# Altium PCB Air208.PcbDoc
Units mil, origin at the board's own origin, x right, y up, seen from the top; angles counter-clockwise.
Board outline 6000 x 4000 mil, 2 copper layers (Top, Bottom), stack 12.7 mil thick; 1 components, 0 nets, 42 pads, 0 vias.
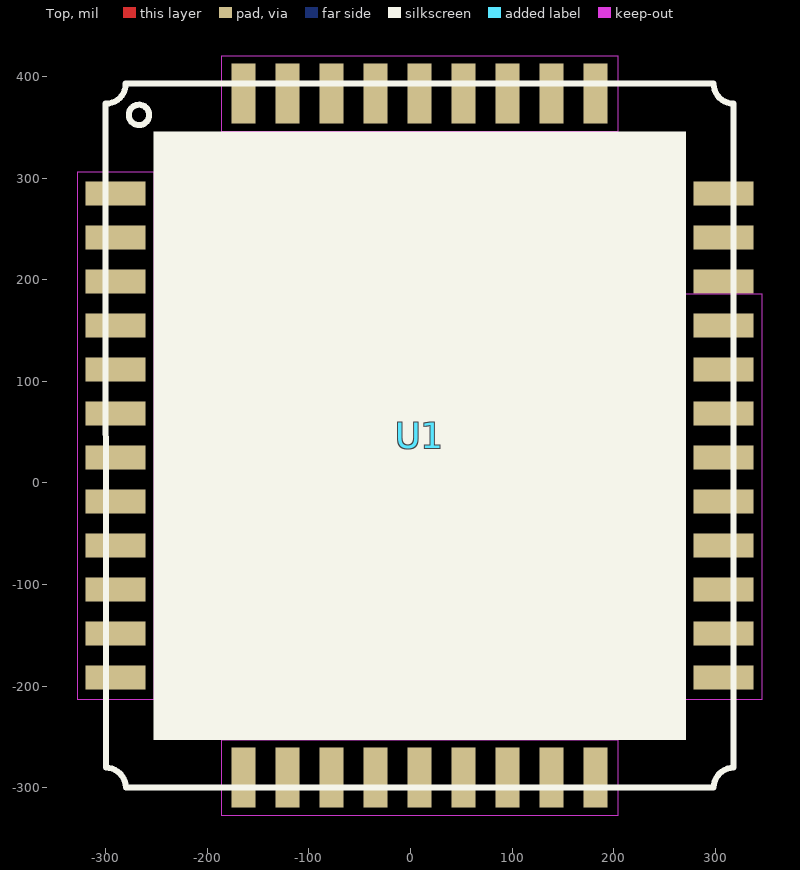
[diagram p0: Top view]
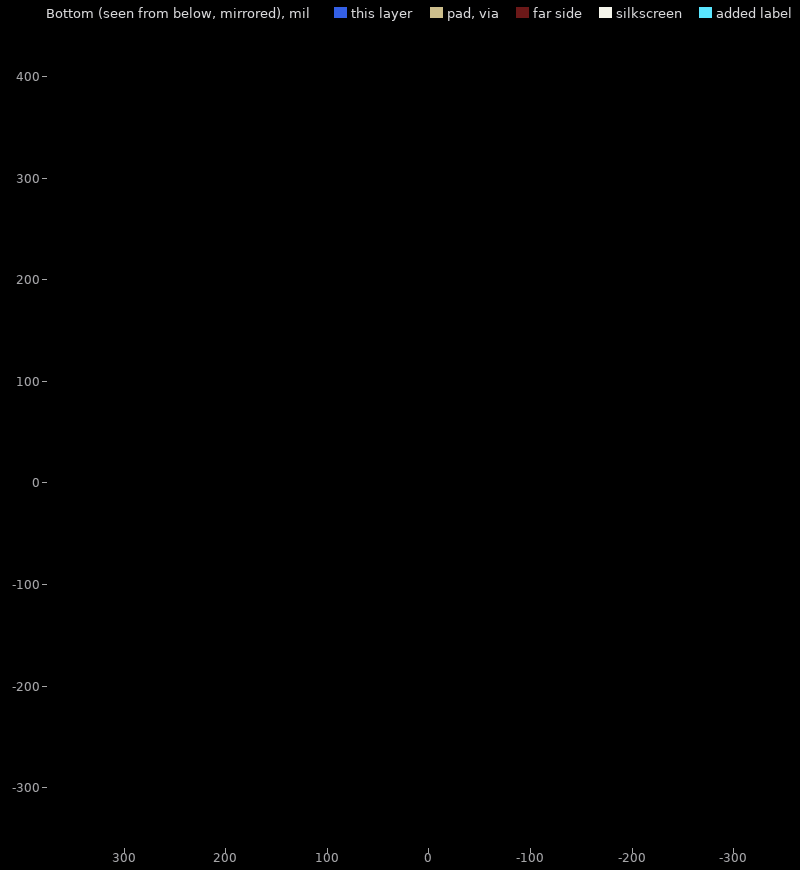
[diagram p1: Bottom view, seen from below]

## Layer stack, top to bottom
Solder Mask Top: solder mask 0.4, Solder Resist, Dk 3.5
Top: signal copper 1.35
Dielectric 1: dielectric 10, FR-4, Dk 4.3
Bottom: signal copper 1.35
Solder Mask Bottom: solder mask 0.4, Solder Resist, Dk 3.5

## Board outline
-9000,-9000 -3000,-9000 -3000,-5000 -9000,-5000

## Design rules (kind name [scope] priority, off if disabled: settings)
Clearance "Clearance - Default - DEFAULT- SMD" [IsVia vs IsSMTPin] p1: gap=6 ignorepadtopadclearanceinfootprint=FALSE
Clearance "Clearance - Default - DEFAULT - Via" [IsVia vs IsVia] p2: gap=6 ignorepadtopadclearanceinfootprint=FALSE
Clearance "Clearance - Default - DEFAULT - Net" [All] p3: gap=6 ignorepadtopadclearanceinfootprint=FALSE except(0: Arc-Hole Track-Hole SMDPad-Hole THPad-Hole Via-Hole Fill-Hole Poly-Hole Region-Hole Text-Hole; 10: Text-Text)
ComponentClearance "ComponentClearance - Default - DEFAULT" [All] p1: gap=6 collisioncheckmode=3 verticalgap=10 showdistances=FALSE
FanoutControl Fanout_Small [(CompPinCount < 5)] p3: bgadir=Out bgaviamode=Centered fanoutstyle=Auto fanoutdirection=OutThenIn viagrid=1 // Fanout_Small (Default Rule)
FanoutControl Fanout_SOIC [IsSOIC] p4: bgadir=Out bgaviamode=Centered fanoutstyle=Auto fanoutdirection=Alternating viagrid=1 // Fanout_SOIC (Default Rule)
HoleToHoleClearance "HoleToHoleClearance - Default - DEFAULT" [All] p1: gap=6 allowstackedmicrovias=TRUE
Length "Default Length" [All] p1: maxlimit=50000 minlimit=0
MaxMinImpedance "Default Impedance" [All] p1: minimum=50.00 maximum=150.0
ParallelSegment "Default Parallel Segment Adjasent" [All] p1: limit=1000 gap=200
ParallelSegment "Default Parallel Segment Same Layer" [All] p2: limit=1000 gap=200
PlaneConnect "Default PlaneConnect" [All] p1: planeconnectstyle=Relief reliefexpansion=20 reliefentries=0 reliefconductorwidth=15 reliefairgap=10
PolygonConnect "PolygonConnect - Default SMT" [IsSMTPin] p1: connectstyle=Relief reliefconductorwidth=10 reliefentries=4 polygonreliefangle="45 Angle" airgapwidth=10
PolygonConnect "PolygonConnect - Default Pad" [All] p2: connectstyle=Relief reliefconductorwidth=15 reliefentries=4 polygonreliefangle="45 Angle" airgapwidth=10
RoutingLayers "RoutingLayers - Default - DEFAULT" [All] p1: top layer_v5=TRUE bottom layer_v5=TRUE
RoutingPriority "RoutingPriority - Default - DEFAULT" [All] p1: routingpriority=3
RoutingTopology "Default Routing Topology" [All] p1: topology=Shortest
RoutingVias "RoutingVias - Default - DEFAULT" [All] p1: holewidth=37 width=55 viastyle="Through Hole" minholewidth=37 minwidth=55 maxholewidth=37 maxwidth=55
SMDToCorner "SMDToCorner - Default - DEFAULT" [All] p1: distance=60000
SolderMaskExpansion [All] p1: expansion=4
Width "Default Width" [All] p1: maxlimit=12 minlimit=12 preferedwidth=12
22 further rules are at their usual default settings.

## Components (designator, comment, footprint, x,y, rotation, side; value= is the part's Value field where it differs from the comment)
U1 "AIR208" AIR208 -300,-300 r0 top

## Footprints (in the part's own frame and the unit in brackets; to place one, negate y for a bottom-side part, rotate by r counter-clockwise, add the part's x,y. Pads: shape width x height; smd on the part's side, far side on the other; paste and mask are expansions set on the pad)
AIR208 [mm]
  rect 1.5x0.6 smd: 1(0.25,14.85) 2(0.25,13.75) 3(0.25,12.65) 4(0.25,11.55) 5(0.25,10.45) 6(0.25,9.35) 7(0.25,8.25) 8(0.25,7.15) 9(0.25,6.05) 10(0.25,4.95) 11(0.25,3.85) 12(0.25,2.75) 22(15.45,2.75) 23(15.45,3.85) 24(15.45,4.95) 25(15.45,6.05) 26(15.45,7.15) 27(15.45,8.25) 28(15.45,9.35) 29(15.45,10.45) 30(15.45,11.55) 31(15.45,12.65) 32(15.45,13.75) 33(15.45,14.85)
  rect 0.6x1.5 smd: 13(3.446,0.25) 14(4.546,0.25) 15(5.646,0.25) 16(6.746,0.25) 17(7.846,0.25) 18(8.946,0.25) 19(10.046,0.25) 20(11.146,0.25) 21(12.246,0.25) 34(12.246,17.35) 35(11.146,17.35) 36(10.046,17.35) 37(8.946,17.35) 38(7.846,17.35) 39(6.746,17.35) 40(5.646,17.35) 41(4.546,17.35) 42(3.446,17.35)
  Top keep-out region: -0.7,15.4 1.2,15.4 1.2,2.2 -0.7,2.2 -0.7,15.4
  Top keep-out region: 2.9,1.2 12.8,1.2 12.8,-0.7 2.9,-0.7 2.9,1.2
  Top keep-out region: 14.5,12.35 16.4,12.35 16.4,2.2 14.5,2.2 14.5,12.35
  Top keep-out region: 2.9,18.3 12.8,18.3 12.8,16.4 2.9,16.4 2.9,18.3
  silkscreen extent 0,0 15.7,17.6

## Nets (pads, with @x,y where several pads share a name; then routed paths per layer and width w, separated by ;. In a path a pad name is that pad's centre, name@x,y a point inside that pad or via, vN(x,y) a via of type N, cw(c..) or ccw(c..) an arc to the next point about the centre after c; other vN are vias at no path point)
pads on no net: U1.1 U1.2 U1.3 U1.4 U1.5 U1.6 U1.7 U1.8 U1.9 U1.10 U1.11 U1.12 U1.13 U1.14 U1.15 U1.16 U1.17 U1.18 U1.19 U1.20 U1.21 U1.22 U1.23 U1.24 U1.25 U1.26 U1.27 U1.28 U1.29 U1.30 U1.31 U1.32 U1.33 U1.34 U1.35 U1.36 U1.37 U1.38 U1.39 U1.40 U1.41 U1.42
